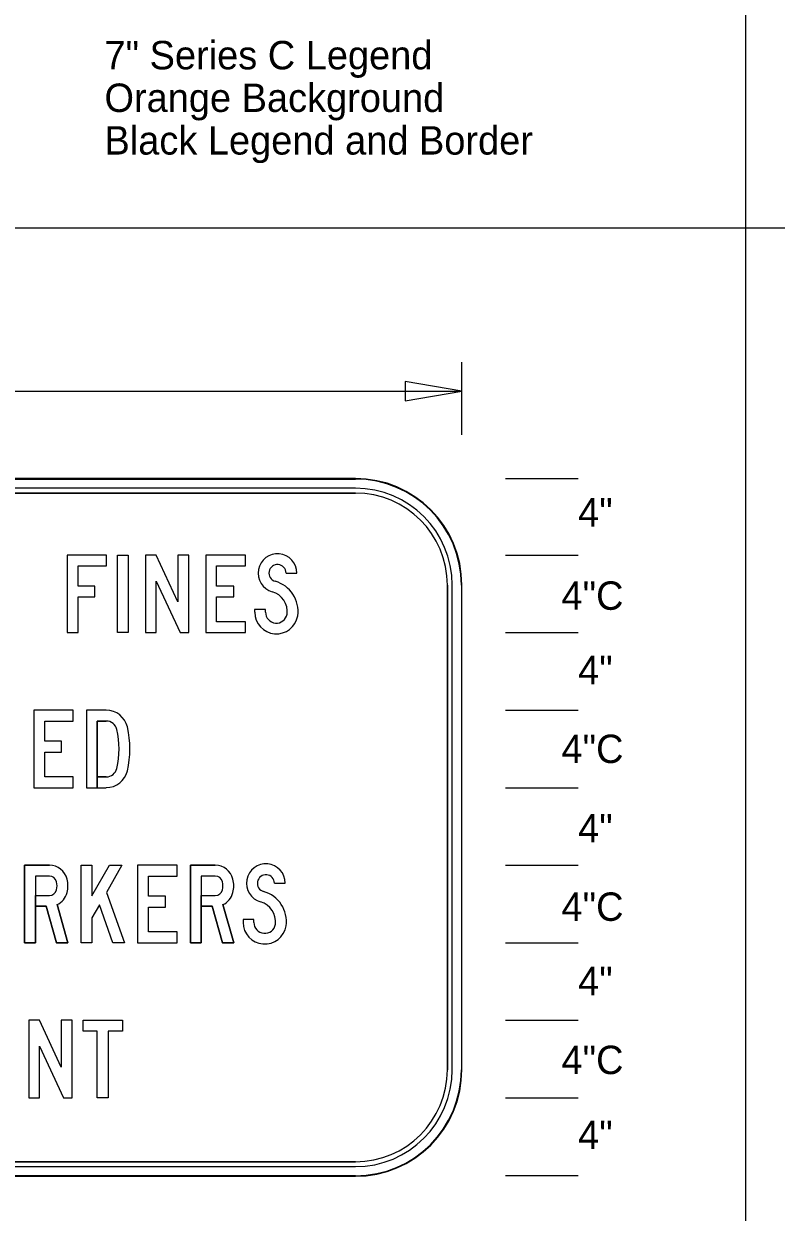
# Model space of a CAD drawing. Extents: x 0 to 770, y 0 to 495.
# Drawn here: x 488.5 to 581.3, y 208.7 to 355.1 of the extents above; entities that cross this region are included whole.
import ezdxf

# ---------------------------------------------------------------- set-up
doc = ezdxf.new("R2010")
doc.units = 0
for name, color, linetype in [('Dimension', 7, 'Continuous'), ('GSBWFill', 7, 'Continuous'), ('GSColorFill', 7, 'Continuous'), ('GSDims', 7, 'Continuous'), ('GSOutline', 7, 'Continuous'), ('SheetLines_dp', 7, 'Continuous'), ('TextStructures', 7, 'Continuous')]:
    doc.layers.add(name, color=color, linetype=linetype)

msp = doc.modelspace()

# ---------------------------------------------------------------- linework, layer by layer
at = {"layer": 'Dimension'}
msp.add_lwpolyline([(542.51, 309.87), (535.49, 311.06), (535.49, 308.68)], close=True, dxfattribs=at)
at = {"layer": 'GSBWFill'}
for p, q in [((529.37, 299.12), (426.69, 299.12)), ((529.37, 297.93), (426.69, 297.93)), ((426.69, 297.33), (529.37, 297.33)), ((520.82, 287.47), (522.16, 287.47)), ((540.71, 285.99), (540.71, 226.29)), ((541.31, 226.29), (541.31, 285.99)), ((542.51, 226.29), (542.51, 285.99)), ((518.29, 282.65), (518.29, 283)), ((498.66, 262.37), (497.56, 262.37)), ((519.39, 249.26), (520.73, 249.26)), ((491.65, 247.76), (491.65, 247.76)), ((512.1, 247.76), (512.1, 247.76)), ((516.86, 244.44), (516.86, 244.8)), ((529.37, 214.95), (426.7, 214.95)), ((426.7, 214.35), (529.37, 214.35)), ((426.69, 213.16), (529.37, 213.16))]:
    msp.add_line(p, q, dxfattribs=at)
for points in [[(495.18, 284.53), (497.27, 284.53), (497.27, 285.87), (495.18, 285.87), (495.18, 288.35), (498.71, 288.35), (498.71, 289.69), (493.84, 289.69), (493.84, 280.14), (495.18, 280.14)], [(500.05, 289.69), (501.38, 289.69), (501.38, 280.14), (500.05, 280.14)], [(507.78, 280.14), (508.84, 280.14), (508.84, 289.69), (507.5, 289.69), (507.5, 283.92), (504.81, 289.69), (503.49, 289.69), (503.49, 280.14), (504.82, 280.14), (504.82, 286.49)], [(512.27, 281.48), (512.27, 284.53), (514.37, 284.53), (514.37, 285.87), (512.27, 285.87), (512.27, 288.35), (515.81, 288.35), (515.81, 289.69), (510.94, 289.69), (510.94, 280.14), (515.81, 280.14), (515.81, 281.48)], [(491.07, 262.37), (491.07, 265.43), (493.16, 265.43), (493.16, 266.77), (491.07, 266.77), (491.07, 269.25), (494.6, 269.25), (494.6, 270.59), (489.73, 270.59), (489.73, 261.03), (494.6, 261.03), (494.6, 262.37)], [(497.81, 246.6), (496.9, 244.99), (496.9, 241.93), (495.56, 241.93), (495.56, 251.48), (496.9, 251.48), (496.9, 247.7), (499.04, 251.48), (500.57, 251.48), (498.68, 248.14), (500.91, 241.93), (499.49, 241.93)], [(503.87, 243.27), (503.87, 246.32), (505.96, 246.32), (505.96, 247.66), (503.87, 247.66), (503.87, 250.14), (507.4, 250.14), (507.4, 251.48), (502.53, 251.48), (502.53, 241.93), (507.4, 241.93), (507.4, 243.27)], [(493.41, 222.83), (494.46, 222.83), (494.46, 232.38), (493.12, 232.38), (493.12, 226.61), (490.43, 232.38), (489.11, 232.38), (489.11, 222.83), (490.45, 222.83), (490.45, 229.18)], [(497.56, 231.04), (495.8, 231.04), (495.8, 232.38), (500.67, 232.38), (500.67, 231.04), (498.9, 231.04), (498.9, 222.83), (497.56, 222.83)]]:
    msp.add_lwpolyline(points, close=True, dxfattribs=at)
for points in [[(518.29, 283), (516.95, 283), (516.95, 282.65)], [(498.66, 270.59), (496.23, 270.59), (496.23, 261.03), (497.56, 261.03), (497.56, 269.25), (498.66, 269.25)], [(497.56, 262.37), (497.56, 261.03), (498.66, 261.03)], [(491.65, 250.14), (489.92, 250.14), (489.92, 241.93), (488.59, 241.93), (488.59, 251.48), (491.65, 251.48)], [(512.1, 250.14), (510.36, 250.14), (510.36, 241.93), (509.03, 241.93), (509.03, 251.48), (512.1, 251.48)], [(492.6, 246.63), (493.93, 241.93), (492.54, 241.93), (491.27, 246.42), (489.92, 246.42), (489.92, 247.76), (491.65, 247.76)], [(513.04, 246.63), (514.38, 241.93), (512.99, 241.93), (511.71, 246.42), (510.36, 246.42), (510.36, 247.76), (512.1, 247.76)], [(516.86, 244.8), (515.52, 244.8), (515.52, 244.44)]]:
    msp.add_lwpolyline(points, dxfattribs=at)
for centre, radius, start, end in [((529.37, 285.99), 13.13, 0, 90), ((529.37, 285.99), 11.94, 0, 90), ((529.37, 285.99), 11.34, 0, 90), ((498.66, 267.91), 2.67, 13.109, 90), ((498.66, 267.91), 1.34, 13.109, 90), ((489.64, 265.81), 10.6, 346.891, 13.109), ((489.64, 265.81), 11.94, 346.891, 13.109), ((498.66, 263.71), 1.34, 270, 346.891), ((498.66, 263.71), 2.67, 270, 346.891), ((512.1, 249.24), 2.24, 13.8865, 90), ((512.1, 249.24), 0.907, 13.8865, 90), ((510.94, 248.95), 2.1, 346.1135, 13.8865), ((510.94, 248.95), 3.44, 346.1135, 13.8865), ((512.1, 248.66), 0.907, 270, 346.1135), ((512.1, 248.66), 2.24, 294.8221, 346.1135), ((529.37, 226.29), 11.94, 270, 0), ((529.37, 226.29), 11.34, 270, 0), ((529.37, 226.29), 13.13, 270, 0)]:
    msp.add_arc(centre, radius, start, end, dxfattribs=at)
for centre, major_axis, start_param, end_param in [((519.77, 287.47), (0, 2.39), 4.712389, 9.149469), ((519.77, 287.47), (0, 1.05), 4.712389, 9.149469), ((518.44, 282.74), (0, 3.87), 4.575028, 6.007876), ((518.44, 282.74), (0, 2.53), 4.582893, 6.007876), ((519.63, 282.65), (0, 2.67), 1.570796, 4.54713), ((519.63, 282.65), (0, 1.34), 1.570796, 4.534115), ((491.65, 249.24), (0, 2.24), 4.954755, 6.283185), ((518.34, 249.26), (0, 2.39), 4.712389, 9.149469), ((491.65, 249.24), (0, 0.907), 4.954755, 6.283185), ((490.5, 248.95), (0, 2.1), 4.470023, 4.954755), ((490.5, 248.95), (0, 3.44), 4.470023, 4.954755), ((518.34, 249.26), (0, 1.05), 4.712389, 9.149469), ((491.65, 248.66), (0, 0.907), 3.141593, 4.470023), ((491.65, 248.66), (0, 2.24), 3.574819, 4.470023), ((517, 244.53), (0, 3.87), 4.575028, 6.007876), ((517, 244.53), (0, 2.53), 4.582893, 6.007876), ((518.2, 244.44), (0, 2.67), 1.570796, 4.54713), ((518.2, 244.44), (0, 1.34), 1.570796, 4.534115)]:
    msp.add_ellipse(centre, major_axis=major_axis, ratio=0.999991, start_param=start_param, end_param=end_param, dxfattribs=at)
at = {"layer": 'GSColorFill'}
for p, q in [((529.37, 299.12), (426.69, 299.12)), ((529.37, 299.12), (426.69, 299.12)), ((426.69, 299.06), (529.37, 299.06)), ((529.37, 297.93), (426.69, 297.93)), ((426.69, 297.33), (529.37, 297.33)), ((520.82, 287.47), (522.16, 287.47)), ((540.71, 285.99), (540.71, 226.29)), ((541.31, 226.29), (541.31, 285.99)), ((542.45, 285.99), (542.45, 226.29)), ((542.51, 226.29), (542.51, 285.99)), ((542.51, 226.29), (542.51, 285.99)), ((518.29, 282.65), (518.29, 283)), ((498.66, 262.37), (497.56, 262.37)), ((519.39, 249.26), (520.73, 249.26)), ((491.65, 247.76), (491.65, 247.76)), ((512.1, 247.76), (512.1, 247.76)), ((516.86, 244.44), (516.86, 244.8)), ((529.37, 214.95), (426.7, 214.95)), ((426.7, 214.35), (529.37, 214.35)), ((529.37, 213.21), (426.69, 213.21)), ((426.69, 213.16), (529.37, 213.16)), ((426.69, 213.16), (529.37, 213.16))]:
    msp.add_line(p, q, dxfattribs=at)
for points in [[(495.18, 284.53), (497.27, 284.53), (497.27, 285.87), (495.18, 285.87), (495.18, 288.35), (498.71, 288.35), (498.71, 289.69), (493.84, 289.69), (493.84, 280.14), (495.18, 280.14)], [(500.05, 289.69), (501.38, 289.69), (501.38, 280.14), (500.05, 280.14)], [(507.78, 280.14), (508.84, 280.14), (508.84, 289.69), (507.5, 289.69), (507.5, 283.92), (504.81, 289.69), (503.49, 289.69), (503.49, 280.14), (504.82, 280.14), (504.82, 286.49)], [(512.27, 281.48), (512.27, 284.53), (514.37, 284.53), (514.37, 285.87), (512.27, 285.87), (512.27, 288.35), (515.81, 288.35), (515.81, 289.69), (510.94, 289.69), (510.94, 280.14), (515.81, 280.14), (515.81, 281.48)], [(491.07, 262.37), (491.07, 265.43), (493.16, 265.43), (493.16, 266.77), (491.07, 266.77), (491.07, 269.25), (494.6, 269.25), (494.6, 270.59), (489.73, 270.59), (489.73, 261.03), (494.6, 261.03), (494.6, 262.37)], [(497.81, 246.6), (496.9, 244.99), (496.9, 241.93), (495.56, 241.93), (495.56, 251.48), (496.9, 251.48), (496.9, 247.7), (499.04, 251.48), (500.57, 251.48), (498.68, 248.14), (500.91, 241.93), (499.49, 241.93)], [(503.87, 243.27), (503.87, 246.32), (505.96, 246.32), (505.96, 247.66), (503.87, 247.66), (503.87, 250.14), (507.4, 250.14), (507.4, 251.48), (502.53, 251.48), (502.53, 241.93), (507.4, 241.93), (507.4, 243.27)], [(493.41, 222.83), (494.46, 222.83), (494.46, 232.38), (493.12, 232.38), (493.12, 226.61), (490.43, 232.38), (489.11, 232.38), (489.11, 222.83), (490.45, 222.83), (490.45, 229.18)], [(497.56, 231.04), (495.8, 231.04), (495.8, 232.38), (500.67, 232.38), (500.67, 231.04), (498.9, 231.04), (498.9, 222.83), (497.56, 222.83)]]:
    msp.add_lwpolyline(points, close=True, dxfattribs=at)
for points in [[(518.29, 283), (516.95, 283), (516.95, 282.65)], [(498.66, 270.59), (496.23, 270.59), (496.23, 261.03), (497.56, 261.03), (497.56, 269.25), (498.66, 269.25)], [(497.56, 262.37), (497.56, 261.03), (498.66, 261.03)], [(491.65, 250.14), (489.92, 250.14), (489.92, 241.93), (488.59, 241.93), (488.59, 251.48), (491.65, 251.48)], [(512.1, 250.14), (510.36, 250.14), (510.36, 241.93), (509.03, 241.93), (509.03, 251.48), (512.1, 251.48)], [(492.6, 246.63), (493.93, 241.93), (492.54, 241.93), (491.27, 246.42), (489.92, 246.42), (489.92, 247.76), (491.65, 247.76)], [(513.04, 246.63), (514.38, 241.93), (512.99, 241.93), (511.71, 246.42), (510.36, 246.42), (510.36, 247.76), (512.1, 247.76)], [(516.86, 244.8), (515.52, 244.8), (515.52, 244.44)]]:
    msp.add_lwpolyline(points, dxfattribs=at)
for centre, radius, start, end in [((529.37, 285.99), 13.13, 0, 90), ((529.37, 285.99), 13.13, 0, 90), ((529.37, 285.99), 13.07, 0, 90), ((529.37, 285.99), 11.94, 0, 90), ((529.37, 285.99), 11.34, 0, 90), ((498.66, 267.91), 2.67, 13.109, 90), ((498.66, 267.91), 1.34, 13.109, 90), ((489.64, 265.81), 10.6, 346.891, 13.109), ((489.64, 265.81), 11.94, 346.891, 13.109), ((498.66, 263.71), 1.34, 270, 346.891), ((498.66, 263.71), 2.67, 270, 346.891), ((512.1, 249.24), 2.24, 13.8865, 90), ((512.1, 249.24), 0.907, 13.8865, 90), ((510.94, 248.95), 2.1, 346.1135, 13.8865), ((510.94, 248.95), 3.44, 346.1135, 13.8865), ((512.1, 248.66), 0.907, 270, 346.1135), ((512.1, 248.66), 2.24, 294.8221, 346.1135), ((529.37, 226.29), 13.13, 270, 0), ((529.37, 226.29), 11.94, 270, 0), ((529.37, 226.29), 11.34, 270, 0), ((529.37, 226.29), 13.13, 270, 0), ((529.37, 226.29), 13.07, 270, 0)]:
    msp.add_arc(centre, radius, start, end, dxfattribs=at)
for centre, major_axis, start_param, end_param in [((519.77, 287.47), (0, 2.39), 4.712389, 9.149469), ((519.77, 287.47), (0, 1.05), 4.712389, 9.149469), ((518.44, 282.74), (0, 3.87), 4.575028, 6.007876), ((518.44, 282.74), (0, 2.53), 4.582893, 6.007876), ((519.63, 282.65), (0, 2.67), 1.570796, 4.54713), ((519.63, 282.65), (0, 1.34), 1.570796, 4.534115), ((491.65, 249.24), (0, 2.24), 4.954755, 6.283185), ((518.34, 249.26), (0, 2.39), 4.712389, 9.149469), ((491.65, 249.24), (0, 0.907), 4.954755, 6.283185), ((490.5, 248.95), (0, 2.1), 4.470023, 4.954755), ((490.5, 248.95), (0, 3.44), 4.470023, 4.954755), ((518.34, 249.26), (0, 1.05), 4.712389, 9.149469), ((491.65, 248.66), (0, 0.907), 3.141593, 4.470023), ((491.65, 248.66), (0, 2.24), 3.574819, 4.470023), ((517, 244.53), (0, 3.87), 4.575028, 6.007876), ((517, 244.53), (0, 2.53), 4.582893, 6.007876), ((518.2, 244.44), (0, 2.67), 1.570796, 4.54713), ((518.2, 244.44), (0, 1.34), 1.570796, 4.534115)]:
    msp.add_ellipse(centre, major_axis=major_axis, ratio=0.999991, start_param=start_param, end_param=end_param, dxfattribs=at)
at = {"layer": 'GSDims'}
for p, q in [((542.51, 304.5), (542.51, 313.45)), ((413.56, 309.87), (542.51, 309.87)), ((547.88, 299.12), (556.83, 299.12)), ((547.88, 289.69), (556.83, 289.69)), ((547.88, 289.69), (556.83, 289.69)), ((547.88, 280.14), (556.83, 280.14)), ((547.88, 280.14), (556.83, 280.14)), ((547.88, 270.59), (556.83, 270.59)), ((547.88, 270.59), (556.83, 270.59)), ((547.88, 261.03), (556.83, 261.03)), ((547.88, 261.03), (556.83, 261.03)), ((547.88, 251.48), (556.83, 251.48)), ((547.88, 251.48), (556.83, 251.48)), ((547.88, 241.93), (556.83, 241.93)), ((547.88, 241.93), (556.83, 241.93)), ((547.88, 232.38), (556.83, 232.38)), ((547.88, 232.38), (556.83, 232.38)), ((547.88, 222.83), (556.83, 222.83)), ((547.88, 222.83), (556.83, 222.83)), ((547.88, 213.27), (556.83, 213.27))]:
    msp.add_line(p, q, dxfattribs=at)
at = {"layer": 'GSOutline'}
for p, q in [((529.37, 299.12), (426.69, 299.12)), ((529.37, 297.93), (426.69, 297.93)), ((529.37, 297.33), (426.69, 297.33)), ((520.82, 287.47), (522.16, 287.47)), ((540.71, 226.29), (540.71, 285.99)), ((541.31, 226.29), (541.31, 285.99)), ((542.51, 226.29), (542.51, 285.99)), ((518.29, 282.65), (518.29, 283)), ((497.56, 262.37), (498.66, 262.37)), ((498.66, 261.03), (498.66, 261.03)), ((491.65, 251.48), (488.59, 251.48)), ((512.1, 251.48), (509.03, 251.48)), ((491.65, 250.14), (491.65, 250.14)), ((512.1, 250.14), (512.1, 250.14)), ((519.39, 249.26), (520.73, 249.26)), ((516.86, 244.44), (516.86, 244.8)), ((426.69, 214.95), (529.37, 214.95)), ((426.69, 214.35), (529.37, 214.35)), ((426.69, 213.16), (529.37, 213.16))]:
    msp.add_line(p, q, dxfattribs=at)
for points in [[(495.18, 284.53), (497.27, 284.53), (497.27, 285.87), (495.18, 285.87), (495.18, 288.35), (498.71, 288.35), (498.71, 289.69), (493.84, 289.69), (493.84, 280.14), (495.18, 280.14)], [(500.05, 289.69), (501.38, 289.69), (501.38, 280.14), (500.05, 280.14)], [(507.78, 280.14), (508.84, 280.14), (508.84, 289.69), (507.5, 289.69), (507.5, 283.92), (504.81, 289.69), (503.49, 289.69), (503.49, 280.14), (504.82, 280.14), (504.82, 286.49)], [(512.27, 281.48), (512.27, 284.53), (514.37, 284.53), (514.37, 285.87), (512.27, 285.87), (512.27, 288.35), (515.81, 288.35), (515.81, 289.69), (510.94, 289.69), (510.94, 280.14), (515.81, 280.14), (515.81, 281.48)], [(491.07, 262.37), (491.07, 265.43), (493.16, 265.43), (493.16, 266.77), (491.07, 266.77), (491.07, 269.25), (494.6, 269.25), (494.6, 270.59), (489.73, 270.59), (489.73, 261.03), (494.6, 261.03), (494.6, 262.37)], [(497.81, 246.6), (496.9, 244.99), (496.9, 241.93), (495.56, 241.93), (495.56, 251.48), (496.9, 251.48), (496.9, 247.7), (499.04, 251.48), (500.57, 251.48), (498.68, 248.14), (500.91, 241.93), (499.49, 241.93)], [(503.87, 243.27), (503.87, 246.32), (505.96, 246.32), (505.96, 247.66), (503.87, 247.66), (503.87, 250.14), (507.4, 250.14), (507.4, 251.48), (502.53, 251.48), (502.53, 241.93), (507.4, 241.93), (507.4, 243.27)], [(493.41, 222.83), (494.46, 222.83), (494.46, 232.38), (493.12, 232.38), (493.12, 226.61), (490.43, 232.38), (489.11, 232.38), (489.11, 222.83), (490.45, 222.83), (490.45, 229.18)], [(497.56, 231.04), (495.8, 231.04), (495.8, 232.38), (500.67, 232.38), (500.67, 231.04), (498.9, 231.04), (498.9, 222.83), (497.56, 222.83)]]:
    msp.add_lwpolyline(points, close=True, dxfattribs=at)
for points in [[(518.29, 283), (516.95, 283), (516.95, 282.65)], [(498.66, 270.59), (496.23, 270.59), (496.23, 261.03), (498.66, 261.03)], [(498.66, 269.25), (497.56, 269.25), (497.56, 262.37)], [(488.59, 251.48), (488.59, 241.93), (489.92, 241.93), (489.92, 246.42), (491.27, 246.42), (492.54, 241.93), (493.93, 241.93), (492.6, 246.63)], [(509.03, 251.48), (509.03, 241.93), (510.36, 241.93), (510.36, 246.42), (511.71, 246.42), (512.99, 241.93), (514.38, 241.93), (513.04, 246.63)], [(491.65, 250.14), (489.92, 250.14), (489.92, 247.76), (491.65, 247.76)], [(512.1, 250.14), (510.36, 250.14), (510.36, 247.76), (512.1, 247.76)], [(516.86, 244.8), (515.52, 244.8), (515.52, 244.44)]]:
    msp.add_lwpolyline(points, dxfattribs=at)
for centre, radius, start, end in [((529.37, 285.99), 13.13, 0, 90), ((529.37, 285.99), 11.94, 0, 90), ((529.37, 285.99), 11.34, 0, 90), ((498.66, 267.91), 2.67, 13.109, 90), ((498.66, 267.91), 1.34, 13.109, 90), ((489.64, 265.81), 10.6, 346.891, 13.109), ((489.64, 265.81), 11.94, 346.891, 13.109), ((498.66, 263.71), 1.34, 270, 346.891), ((498.66, 263.71), 2.67, 270, 346.891), ((512.1, 249.24), 2.24, 13.8865, 90), ((512.1, 249.24), 0.907, 13.8865, 90), ((510.94, 248.95), 2.1, 346.1135, 13.8865), ((510.94, 248.95), 3.44, 346.1135, 13.8865), ((512.1, 248.66), 0.907, 270, 346.1135), ((512.1, 248.66), 2.24, 294.8221, 346.1135), ((529.37, 226.29), 11.94, 270, 0), ((529.37, 226.29), 11.34, 270, 0), ((529.37, 226.29), 13.13, 270, 0)]:
    msp.add_arc(centre, radius, start, end, dxfattribs=at)
for centre, major_axis, start_param, end_param in [((519.77, 287.47), (0, 2.39), 4.712389, 9.149469), ((519.77, 287.47), (0, 1.05), 4.712389, 9.149469), ((518.44, 282.74), (0, 3.87), 4.575028, 6.007876), ((518.44, 282.74), (0, 2.53), 4.582893, 6.007876), ((519.63, 282.65), (0, 2.67), 1.570796, 4.54713), ((519.63, 282.65), (0, 1.34), 1.570796, 4.534115), ((491.65, 249.24), (0, 2.24), 4.954755, 6.283185), ((518.34, 249.26), (0, 2.39), 4.712389, 9.149469), ((491.65, 249.24), (0, 0.907), 4.954755, 6.283185), ((490.5, 248.95), (0, 2.1), 4.470023, 4.954755), ((490.5, 248.95), (0, 3.44), 4.470023, 4.954755), ((518.34, 249.26), (0, 1.05), 4.712389, 9.149469), ((491.65, 248.66), (0, 0.907), 3.141593, 4.470023), ((491.65, 248.66), (0, 2.24), 3.574819, 4.470023), ((517, 244.53), (0, 3.87), 4.575028, 6.007876), ((517, 244.53), (0, 2.53), 4.582893, 6.007876), ((518.2, 244.44), (0, 2.67), 1.570796, 4.54713), ((518.2, 244.44), (0, 1.34), 1.570796, 4.534115)]:
    msp.add_ellipse(centre, major_axis=major_axis, ratio=0.999991, start_param=start_param, end_param=end_param, dxfattribs=at)
at = {"layer": 'SheetLines_dp'}
for p, q in [((577.5, 0), (577.5, 495)), ((0, 330), (770, 330))]:
    msp.add_line(p, q, dxfattribs=at)

# ---------------------------------------------------------------- texts
at = {"layer": 'TextStructures'}
for s, p in [('7" Series C Legend', (498.44, 349.53)), ('Orange Background', (498.44, 344.28)), ('Black Legend and Border  ', (498.44, 339.03)), ('4"', (556.83, 293.21)), ('4"C', (554.78, 282.95)), ('4"', (556.83, 273.78)), ('4"C', (554.78, 264.07)), ('4"', (556.83, 254.29)), ('4"C', (554.78, 244.63)), ('4"', (556.83, 235.47)), ('4"C', (554.78, 225.75)), ('4"', (556.83, 216.53))]:
    msp.add_text(s, height=3.5, dxfattribs=at).set_placement(p)

doc.saveas('drawing.dxf')
